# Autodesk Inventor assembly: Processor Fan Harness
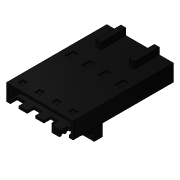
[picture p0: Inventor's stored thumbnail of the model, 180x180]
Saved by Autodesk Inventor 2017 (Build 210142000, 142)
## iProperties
Created: 2007-02
Part Number: Processor Fan Harness
Document SubType Name: Assembly
Designer: DanielSeverino
Author: DanielSeverino
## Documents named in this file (2)
- C:\Users\DanielSeverino\Desktop\01\Processor Fan Harness.iam
- C:\Users\DanielSeverino\Desktop\01\Fan Connector.ipt
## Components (1 placed, 1 different names)
1. Fan Connector:1
